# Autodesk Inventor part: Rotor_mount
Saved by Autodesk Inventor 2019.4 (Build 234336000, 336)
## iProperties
Created: 2020-04
Part Number: Rotor_mount
Material: Generic
Document SubType Name: Modeling
Designer: Administrator
Density: 1 g/cm^3
Appearance: Default
Title: Rotor_mount v9
Author: Administrator
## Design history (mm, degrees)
feature "Body2"
body "Solid1"
